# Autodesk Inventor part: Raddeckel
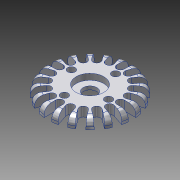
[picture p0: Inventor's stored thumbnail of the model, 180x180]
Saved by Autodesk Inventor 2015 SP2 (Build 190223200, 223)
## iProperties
Created: 2012-07
Part Number: Raddeckel
Material: Aluminium 6061
Document SubType Name: Modeling
Designer: rYan
Mass: 5.08801 g
Surface Area: 32.6854 cm^2
Volume: 1.8775 cm^3
Density: 2.71 g/cm^3
Appearance: Aluminium - flach
Author: rYan
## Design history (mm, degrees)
sketch "Skizze1"
  geometry: C1 r 24.5 at (0, 0); A1 r 22.5 centre (0, 0) between (2, 22.411) and (-2, 22.411) reference; 1 further point
  constraints: 2 centre point, 2 point on circle, 1 coincident, 4 other
  dimensions: "d28" = 49 diameter of C1
extrude "Extrusion1" new body sketch "Skizze1" distance "d0" = 5.5; taper "d1" = 0 deg
fillet "Rundung1" dims "d31" = 4
sketch "Skizze2"
  geometry: L1 (-2.2, 24.5)-(2.2, 24.5); L2 (2.2, 24.5)-(2.2, 17.7); L3 (-2.2, 24.5)-(-2.2, 17.7); L4 (0, 31.333)-(0, -31.333); L5 (0, 43.866)-(0, -43.866) reference; C1 r 15.5 at (0, 0); C2 r 24.5 at (0, 0) reference; A1 r 2.2 centre (0, 17.7) between (-2.2, 17.7) and (2.2, 17.7); 2 further points
  constraints: 8 end point, 4 tangent, 2 centre point, 2 coincident, 2 point on circle, 1 collinear, 1 midpoint, 1 parallel, 1 perpendicular, 1 other
  dimensions: "d2" = 31 diameter of C1; "d3" = 4.4 distance between parallel lines of L2 L3
extrude "Extrusion2" cut sketch "Skizze2" stored distance "d4" = 2; taper "d5" = 0 deg
sketch "Skizze3"
  geometry: 1 further point
hole "Bohrung1" sketch "Skizze3" at (0, 0) diameter "d9" = 8; stored, may be unused: countersink angle "d13" = 90 deg, drill point angle "d15" = 118 deg; dims "d10" = 6, "d11" = 16, "d12" = 3.5, "d14" = 8
sketch "Skizze5" dims "d29" = 26
  geometry: L1 (0, 34.3)-(0, -34.3) reference; L2 (-34.3, 0)-(34.3, 0) reference; L3 (0, 0)-(-2.034, -12.84); 1 further point
  constraints: 2 end point, 1 coincident, 3 other
  dimensions: "d30" = 9 deg angle of L1 L3
hole "Bohrung2" sketch "Skizze5" at (-2.034, -12.84) diameter "d18" = 2.1; stored, may be unused: countersink angle "d22" = 90 deg, drill point angle "d24" = 118 deg; dims "d19" = 6, "d20" = 4.4, "d21" = 4, "d23" = 8
pattern_circular "Runde Anordnung2" dims angle "d26" = 360 deg
node "Volumenkörper1"
pattern_circular "Runde Anordnung1" dims angle "d7" = 360 deg
